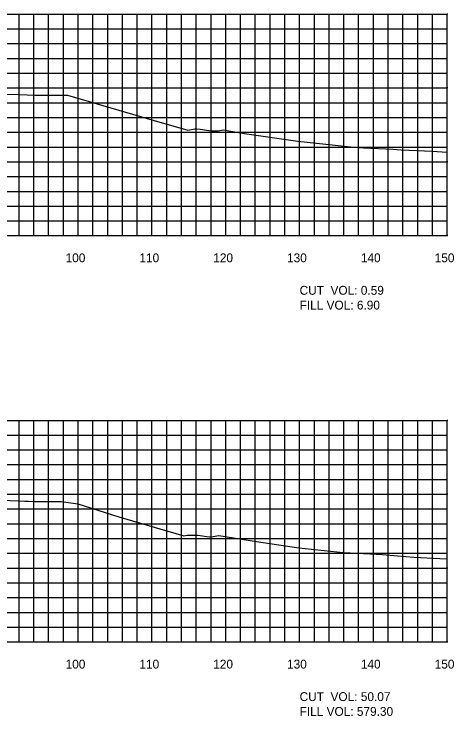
# Model space of a CAD drawing. Extents: x 1800880 to 1818864, y 245271 to 250560.
# Drawn here: x 1805102.3 to 1805161.9, y 250089.4 to 250184.4 of the extents above; entities that cross this region are included whole.
import ezdxf

# ---------------------------------------------------------------- set-up
doc = ezdxf.new("R2010")
doc.units = 0
for name, color, linetype in [('CL-CNST', 7, 'Continuous'), ('DESIGN - DRAINAGE - Bridges', 7, 'Continuous'), ('DRAINAGETXT', 7, 'Continuous'), ('Level 46', 7, 'Continuous')]:
    doc.layers.add(name, color=color, linetype=linetype)

msp = doc.modelspace()

# ---------------------------------------------------------------- linework, layer by layer
at = {"layer": 'CL-CNST'}
for points in [[(1805096.472, 250173.73), (1805102.915, 250173.522), (1805103.014, 250173.518), (1805104.111, 250173.476), (1805105.181, 250173.462), (1805106.972, 250173.462), (1805109.157, 250173.462), (1805109.438, 250173.459), (1805109.548, 250173.46), (1805121.303, 250170), (1805125.862, 250168.709), (1805126.807, 250168.902), (1805127.08, 250168.902), (1805127.516, 250168.837), (1805129.019, 250168.612), (1805129.962, 250168.612), (1805130.625, 250168.748), (1805133.549, 250168.266), (1805140.77, 250167.226), (1805148.37, 250166.392), (1805149.657, 250166.335), (1805153.678, 250166.157), (1805154.19, 250166.102), (1805154.76, 250166.064), (1805158.965, 250165.848), (1805161.002, 250165.732)], [(1805100.702, 250118.605), (1805102.852, 250118.535), (1805103.793, 250118.497), (1805104.254, 250118.479), (1805105.132, 250118.462), (1805107.098, 250118.462), (1805108.71, 250118.462), (1805110.347, 250118.208), (1805110.943, 250118.116), (1805116.503, 250116.378), (1805123.134, 250114.427), (1805125.312, 250113.81), (1805125.764, 250113.902), (1805127.206, 250113.902), (1805128.734, 250113.673), (1805129.299, 250113.69), (1805130.075, 250113.849), (1805135.177, 250113.009), (1805140.893, 250112.185), (1805146.909, 250111.525), (1805148.809, 250111.441), (1805152.217, 250111.29), (1805154.252, 250111.072), (1805156.514, 250110.92), (1805159.993, 250110.741), (1805161.002, 250110.684)]]:
    msp.add_lwpolyline(points, dxfattribs=at)
at = {"layer": 'DESIGN - DRAINAGE - Bridges'}
for p, q in [((1805161.002, 250154.432), (1805161.002, 250184.432)), ((1805161.062, 250184.432), (1805161.002, 250184.432)), ((1805161.062, 250174.432), (1805161.002, 250174.432)), ((1805161.062, 250164.432), (1805161.002, 250164.432)), ((1804861.002, 250154.432), (1805161.002, 250154.432)), ((1805111.002, 250154.372), (1805111.002, 250154.432)), ((1805121.002, 250154.372), (1805121.002, 250154.432)), ((1805131.002, 250154.372), (1805131.002, 250154.432)), ((1805141.002, 250154.372), (1805141.002, 250154.432)), ((1805151.002, 250154.372), (1805151.002, 250154.432)), ((1805161.002, 250154.372), (1805161.002, 250154.432)), ((1805161.062, 250154.432), (1805161.002, 250154.432)), ((1805161.002, 250099.432), (1805161.002, 250129.432)), ((1805161.062, 250129.432), (1805161.002, 250129.432)), ((1805161.062, 250119.432), (1805161.002, 250119.432)), ((1805161.062, 250109.432), (1805161.002, 250109.432)), ((1804861.002, 250099.432), (1805161.002, 250099.432)), ((1805111.002, 250099.372), (1805111.002, 250099.432)), ((1805121.002, 250099.372), (1805121.002, 250099.432)), ((1805131.002, 250099.372), (1805131.002, 250099.432)), ((1805141.002, 250099.372), (1805141.002, 250099.432)), ((1805151.002, 250099.372), (1805151.002, 250099.432)), ((1805161.002, 250099.372), (1805161.002, 250099.432)), ((1805161.062, 250099.432), (1805161.002, 250099.432))]:
    msp.add_line(p, q, dxfattribs=at)
at = {"layer": 'Level 46'}
for p, q in [((1804861.002, 250184.432), (1805161.002, 250184.432)), ((1805103.002, 250154.432), (1805103.002, 250184.432)), ((1805105.002, 250154.432), (1805105.002, 250184.432)), ((1805107.002, 250154.432), (1805107.002, 250184.432)), ((1805109.002, 250154.432), (1805109.002, 250184.432)), ((1805111.002, 250154.432), (1805111.002, 250184.432)), ((1805113.002, 250154.432), (1805113.002, 250184.432)), ((1805115.002, 250154.432), (1805115.002, 250184.432)), ((1805117.002, 250154.432), (1805117.002, 250184.432)), ((1805119.002, 250154.432), (1805119.002, 250184.432)), ((1805121.002, 250154.432), (1805121.002, 250184.432)), ((1805123.002, 250154.432), (1805123.002, 250184.432)), ((1805125.002, 250154.432), (1805125.002, 250184.432)), ((1805127.002, 250154.432), (1805127.002, 250184.432)), ((1805129.002, 250154.432), (1805129.002, 250184.432)), ((1805131.002, 250154.432), (1805131.002, 250184.432)), ((1805133.002, 250154.432), (1805133.002, 250184.432)), ((1805135.002, 250154.432), (1805135.002, 250184.432)), ((1805137.002, 250154.432), (1805137.002, 250184.432)), ((1805139.002, 250154.432), (1805139.002, 250184.432)), ((1805141.002, 250154.432), (1805141.002, 250184.432)), ((1805143.002, 250154.432), (1805143.002, 250184.432)), ((1805145.002, 250154.432), (1805145.002, 250184.432)), ((1805147.002, 250154.432), (1805147.002, 250184.432)), ((1805149.002, 250154.432), (1805149.002, 250184.432)), ((1805151.002, 250154.432), (1805151.002, 250184.432)), ((1805153.002, 250154.432), (1805153.002, 250184.432)), ((1805155.002, 250154.432), (1805155.002, 250184.432)), ((1805157.002, 250154.432), (1805157.002, 250184.432)), ((1805159.002, 250154.432), (1805159.002, 250184.432)), ((1805161.002, 250154.432), (1805161.002, 250184.432)), ((1804861.002, 250182.432), (1805161.002, 250182.432)), ((1804861.002, 250180.432), (1805161.002, 250180.432)), ((1804861.002, 250178.432), (1805161.002, 250178.432)), ((1804861.002, 250176.432), (1805161.002, 250176.432)), ((1804861.002, 250174.432), (1805161.002, 250174.432)), ((1804861.002, 250172.432), (1805161.002, 250172.432)), ((1804861.002, 250170.432), (1805161.002, 250170.432)), ((1804861.002, 250168.432), (1805161.002, 250168.432)), ((1804861.002, 250166.432), (1805161.002, 250166.432)), ((1804861.002, 250164.432), (1805161.002, 250164.432)), ((1804861.002, 250162.432), (1805161.002, 250162.432)), ((1804861.002, 250160.432), (1805161.002, 250160.432)), ((1804861.002, 250158.432), (1805161.002, 250158.432)), ((1804861.002, 250156.432), (1805161.002, 250156.432)), ((1804861.002, 250154.432), (1805161.002, 250154.432)), ((1804861.002, 250129.432), (1805161.002, 250129.432)), ((1805103.002, 250099.432), (1805103.002, 250129.432)), ((1805105.002, 250099.432), (1805105.002, 250129.432)), ((1805107.002, 250099.432), (1805107.002, 250129.432)), ((1805109.002, 250099.432), (1805109.002, 250129.432)), ((1805111.002, 250099.432), (1805111.002, 250129.432)), ((1805113.002, 250099.432), (1805113.002, 250129.432)), ((1805115.002, 250099.432), (1805115.002, 250129.432)), ((1805117.002, 250099.432), (1805117.002, 250129.432)), ((1805119.002, 250099.432), (1805119.002, 250129.432)), ((1805121.002, 250099.432), (1805121.002, 250129.432)), ((1805123.002, 250099.432), (1805123.002, 250129.432)), ((1805125.002, 250099.432), (1805125.002, 250129.432)), ((1805127.002, 250099.432), (1805127.002, 250129.432)), ((1805129.002, 250099.432), (1805129.002, 250129.432)), ((1805131.002, 250099.432), (1805131.002, 250129.432)), ((1805133.002, 250099.432), (1805133.002, 250129.432)), ((1805135.002, 250099.432), (1805135.002, 250129.432)), ((1805137.002, 250099.432), (1805137.002, 250129.432)), ((1805139.002, 250099.432), (1805139.002, 250129.432)), ((1805141.002, 250099.432), (1805141.002, 250129.432)), ((1805143.002, 250099.432), (1805143.002, 250129.432)), ((1805145.002, 250099.432), (1805145.002, 250129.432)), ((1805147.002, 250099.432), (1805147.002, 250129.432)), ((1805149.002, 250099.432), (1805149.002, 250129.432)), ((1805151.002, 250099.432), (1805151.002, 250129.432)), ((1805153.002, 250099.432), (1805153.002, 250129.432)), ((1805155.002, 250099.432), (1805155.002, 250129.432)), ((1805157.002, 250099.432), (1805157.002, 250129.432)), ((1805159.002, 250099.432), (1805159.002, 250129.432)), ((1805161.002, 250099.432), (1805161.002, 250129.432)), ((1804861.002, 250127.432), (1805161.002, 250127.432)), ((1804861.002, 250125.432), (1805161.002, 250125.432)), ((1804861.002, 250123.432), (1805161.002, 250123.432)), ((1804861.002, 250121.432), (1805161.002, 250121.432)), ((1804861.002, 250119.432), (1805161.002, 250119.432)), ((1804861.002, 250117.432), (1805161.002, 250117.432)), ((1804861.002, 250115.432), (1805161.002, 250115.432)), ((1804861.002, 250113.432), (1805161.002, 250113.432)), ((1804861.002, 250111.432), (1805161.002, 250111.432)), ((1804861.002, 250109.432), (1805161.002, 250109.432)), ((1804861.002, 250107.432), (1805161.002, 250107.432)), ((1804861.002, 250105.432), (1805161.002, 250105.432)), ((1804861.002, 250103.432), (1805161.002, 250103.432)), ((1804861.002, 250101.432), (1805161.002, 250101.432)), ((1804861.002, 250099.432), (1805161.002, 250099.432))]:
    msp.add_line(p, q, dxfattribs=at)

# ---------------------------------------------------------------- texts
for s, p in [('100', (1805109.301, 250150.832)), ('110', (1805119.301, 250150.832)), ('120', (1805129.301, 250150.832)), ('130', (1805139.301, 250150.832)), ('140', (1805149.301, 250150.832)), ('150', (1805159.301, 250150.832)), ('100', (1805109.301, 250095.832)), ('110', (1805119.301, 250095.832)), ('120', (1805129.301, 250095.832)), ('130', (1805139.301, 250095.832)), ('140', (1805149.301, 250095.832)), ('150', (1805159.301, 250095.832))]:
    msp.add_text(s, height=1.2).set_placement(p)
at = {"layer": 'DRAINAGETXT'}
for s, p in [('CUT  VOL: 0.59', (1805141.002, 250146.432)), ('FILL VOL: 6.90', (1805141.002, 250144.432)), ('CUT  VOL: 50.07', (1805141.002, 250091.432)), ('FILL VOL: 579.30', (1805141.002, 250089.432))]:
    msp.add_text(s, height=1.2, dxfattribs=at).set_placement(p)

doc.saveas('drawing.dxf')
